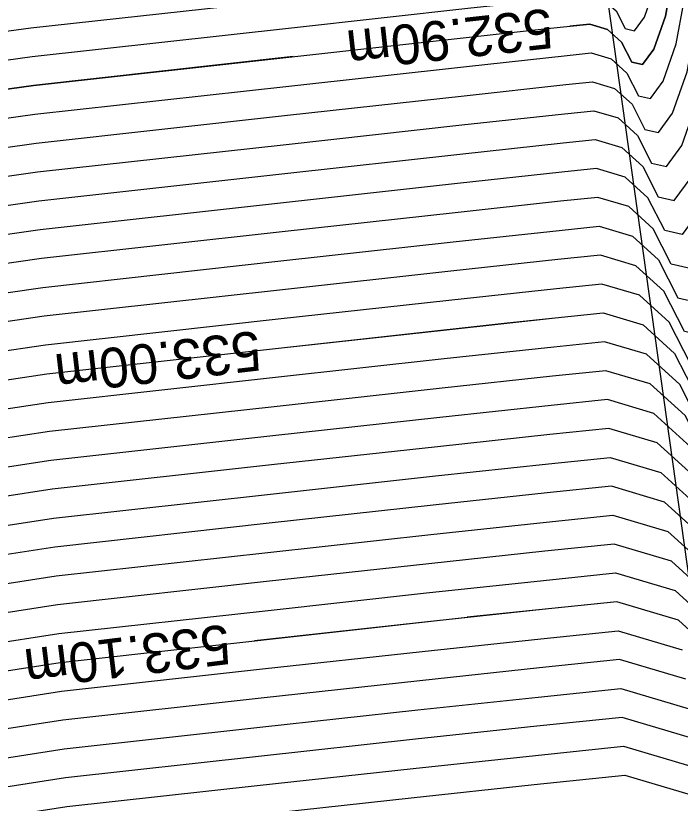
# Model space of a CAD drawing. Extents: x -866683 to -866410, y -1041951 to -1040252.
# Drawn here: x -866459.87 to -866454.85, y -1041930.1 to -1041924.15 of the extents above; entities that cross this region are included whole.
import ezdxf

# ---------------------------------------------------------------- set-up
doc = ezdxf.new("R2010")
doc.units = 0
for name, color, linetype in [('BREAKLINE', 7, 'Continuous'), ('V-HL', 7, 'Continuous'), ('V-VEDL', 7, 'Continuous'), ('V_po_cm', 7, 'Continuous')]:
    doc.layers.add(name, color=color, linetype=linetype)

msp = doc.modelspace()

# ---------------------------------------------------------------- linework, layer by layer
at = {"layer": 'BREAKLINE'}
msp.add_lwpolyline([(-866451.679, -1041950.508), (-866455.618, -1041922.473), (-866456.719, -1041912.396), (-866455.207, -1041909.853), (-866453.752, -1041908.342), (-866450, -1041907.538), (-866447.7, -1041908.076), (-866445.165, -1041909.459), (-866437.422, -1041915.176), (-866426.565, -1041925.108), (-866438.22, -1041915.868), (-866445.312, -1041910.554), (-866447.7, -1041908.076)], dxfattribs=at)
at = {"layer": 'V-HL'}
for points in [[(-866456.1597, -1041926.4733), (-866455.4344, -1041926.3983), (-866455.1343, -1041926.4876), (-866454.8967, -1041926.7037), (-866454.7217, -1041927.0466), (-866454.5387, -1041927.0874), (-866454.3478, -1041926.8261), (-866454.1489, -1041926.2626), (-866454.1234, -1041926.1239)], [(-866461.9223, -1041927.5304), (-866461.5568, -1041927.2112), (-866460.8556, -1041927.0405), (-866459.6359, -1041926.8588), (-866456.1597, -1041926.4733)]]:
    msp.add_lwpolyline(points, dxfattribs=at)
at = {"layer": 'V-VEDL'}
for points in [[(-866455.8588, -1041924.2509), (-866455.5364, -1041924.2176), (-866455.403, -1041924.2573), (-866455.2974, -1041924.3533), (-866455.2196, -1041924.5057), (-866455.1383, -1041924.5239), (-866455.0534, -1041924.4077), (-866454.9651, -1041924.1572), (-866454.9139, -1041923.8786), (-866454.9, -1041923.5718), (-866454.9234, -1041923.2368), (-866454.3666, -1041923.0849), (-866453.2296, -1041923.1162), (-866449.7953, -1041923.5448)], [(-866449.7169, -1041924.4172), (-866452.0847, -1041924.1217), (-866452.8467, -1041924.414), (-866453.1868, -1041925.1464), (-866453.1051, -1041926.3188), (-866453.1537, -1041927.3927), (-866453.3327, -1041928.3679), (-866453.6421, -1041929.2445), (-866453.9391, -1041929.651), (-866454.2237, -1041929.5876), (-866454.496, -1041929.0541), (-866454.8656, -1041928.7179), (-866455.3324, -1041928.579), (-866456.4607, -1041928.6957)], [(-866462.1228, -1041925.2864), (-866461.8248, -1041925.0261), (-866461.0792, -1041924.8677), (-866459.7368, -1041924.6809), (-866455.8588, -1041924.2509)], [(-866465.5755, -1041931.3671), (-866464.7785, -1041933.0499), (-866464.3707, -1041933.5335), (-866463.9536, -1041933.6594), (-866463.5272, -1041933.4274), (-866463.09, -1041933.2561), (-866462.6419, -1041933.1454), (-866462.1831, -1041933.0953), (-866461.8794, -1041932.6906), (-866461.731, -1041931.9311), (-866461.7378, -1041930.817), (-866461.7316, -1041930.0749), (-866461.7123, -1041929.7051), (-866461.68, -1041929.7074), (-866461.5945, -1041929.6531), (-866461.4558, -1041929.5422), (-866461.264, -1041929.3746), (-866460.6237, -1041929.2061), (-866459.535, -1041929.0366), (-866456.4607, -1041928.6957)]]:
    msp.add_lwpolyline(points, dxfattribs=at)
at = {"layer": 'V_po_cm'}
for points in [[(-866462.1629, -1041924.8375), (-866461.8784, -1041924.5891), (-866461.1239, -1041924.4331), (-866459.757, -1041924.2454), (-866457.7778, -1041924.0259), (-866456.418, -1041923.8754), (-866455.6777, -1041923.7939), (-866455.5568, -1041923.7814), (-866455.4568, -1041923.8112), (-866455.3776, -1041923.8832), (-866455.3192, -1041923.9975), (-866455.2582, -1041924.0111), (-866455.1946, -1041923.924), (-866455.1283, -1041923.7362), (-866455.0899, -1041923.5272), (-866455.0795, -1041923.2971), (-866455.097, -1041923.0459), (-866454.5186, -1041922.952), (-866453.3441, -1041923.0156), (-866451.5736, -1041923.2366), (-866450.2422, -1041923.3441), (-866449.3499, -1041923.3382), (-866448.8966, -1041923.2189)], [(-866462.1428, -1041925.062), (-866461.8516, -1041924.8076), (-866461.1015, -1041924.6504), (-866459.7469, -1041924.4632), (-866457.7878, -1041924.2459), (-866456.4347, -1041924.0962), (-866455.6876, -1041924.0141), (-866455.5466, -1041923.9995), (-866455.4299, -1041924.0342), (-866455.3375, -1041924.1183), (-866455.2694, -1041924.2516), (-866455.1983, -1041924.2675), (-866455.124, -1041924.1659), (-866455.0467, -1041923.9467), (-866455.0019, -1041923.7029), (-866454.9898, -1041923.4345), (-866455.0102, -1041923.1413), (-866454.4426, -1041923.0185), (-866453.2868, -1041923.0659), (-866451.543, -1041923.2835), (-866450.2317, -1041923.3894), (-866449.3528, -1041923.3836), (-866448.9063, -1041923.2661)], [(-866452.7723, -1041923.1732), (-866453.2296, -1041923.1162), (-866454.3666, -1041923.0849), (-866454.9234, -1041923.2368), (-866454.9, -1041923.5718), (-866454.9139, -1041923.8786), (-866454.9651, -1041924.1572), (-866455.0534, -1041924.4077), (-866455.1383, -1041924.5239), (-866455.2196, -1041924.5057), (-866455.2974, -1041924.3533), (-866455.403, -1041924.2573), (-866455.5364, -1041924.2176), (-866455.688, -1041924.2333)], [(-866462.1027, -1041925.5108), (-866461.798, -1041925.2446), (-866461.0568, -1041925.085), (-866459.7267, -1041924.8987), (-866457.8078, -1041924.6859), (-866456.4681, -1041924.5378), (-866455.7075, -1041924.4544), (-866455.5262, -1041924.4356), (-866455.3761, -1041924.4803), (-866455.2574, -1041924.5883), (-866455.1698, -1041924.7598), (-866455.0783, -1041924.7802), (-866454.9829, -1041924.6495), (-866454.8834, -1041924.3678), (-866454.8259, -1041924.0543), (-866454.8103, -1041923.7092), (-866454.8365, -1041923.3323), (-866454.2906, -1041923.1514), (-866453.1723, -1041923.1664), (-866451.4819, -1041923.3774), (-866450.2106, -1041923.4801), (-866449.3586, -1041923.4745), (-866448.9258, -1041923.3605)], [(-866462.0827, -1041925.7352), (-866461.7712, -1041925.4631), (-866461.0344, -1041925.3022), (-866459.7166, -1041925.1165), (-866457.8178, -1041924.906), (-866456.4847, -1041924.7586), (-866455.7175, -1041924.6745), (-866455.516, -1041924.6537), (-866455.3493, -1041924.7033), (-866455.2173, -1041924.8234), (-866455.12, -1041925.0139), (-866455.0184, -1041925.0366), (-866454.9123, -1041924.8914), (-866454.8018, -1041924.5783), (-866454.7379, -1041924.23), (-866454.7205, -1041923.8465), (-866454.7497, -1041923.4278), (-866454.2146, -1041923.2178), (-866453.1151, -1041923.2167), (-866451.4513, -1041923.4244), (-866450.2001, -1041923.5254), (-866449.3615, -1041923.5199), (-866448.9355, -1041923.4077)], [(-866462.0626, -1041925.9596), (-866461.7444, -1041925.6816), (-866461.0121, -1041925.5195), (-866459.7065, -1041925.3343), (-866457.8278, -1041925.126), (-866456.5014, -1041924.9794), (-866455.7274, -1041924.8947), (-866455.5058, -1041924.8718), (-866455.3224, -1041924.9263), (-866455.1772, -1041925.0584), (-866455.0702, -1041925.268), (-866454.9584, -1041925.2929), (-866454.8417, -1041925.1332), (-866454.7202, -1041924.7888), (-866454.6499, -1041924.4057), (-866454.6308, -1041923.9839), (-866454.6629, -1041923.5233), (-866454.1386, -1041923.2843), (-866453.0579, -1041923.267), (-866451.4207, -1041923.4713), (-866450.1896, -1041923.5708), (-866449.3644, -1041923.5653), (-866448.9453, -1041923.4549)], [(-866462.0426, -1041926.184), (-866461.7176, -1041925.9001), (-866460.9897, -1041925.7368), (-866459.6965, -1041925.5521), (-866457.8378, -1041925.346), (-866456.5181, -1041925.2002), (-866455.7374, -1041925.1149), (-866455.4956, -1041925.0898), (-866455.2955, -1041925.1494), (-866455.1371, -1041925.2935), (-866455.0204, -1041925.5221), (-866454.8985, -1041925.5493), (-866454.7712, -1041925.3751), (-866454.6386, -1041924.9994), (-866454.5619, -1041924.5814), (-866454.541, -1041924.1212), (-866454.5761, -1041923.6187), (-866454.0626, -1041923.3508), (-866453.0006, -1041923.3173), (-866451.3901, -1041923.5183), (-866450.179, -1041923.6161), (-866449.3673, -1041923.6107), (-866448.955, -1041923.5022)], [(-866448.9647, -1041923.5494), (-866449.3702, -1041923.6561), (-866450.1685, -1041923.6614), (-866451.3595, -1041923.5652), (-866452.9434, -1041923.3675), (-866453.9866, -1041923.4172), (-866454.4892, -1041923.7142), (-866454.4513, -1041924.2586), (-866454.4739, -1041924.7571), (-866454.557, -1041925.2099), (-866454.7006, -1041925.6169), (-866454.8385, -1041925.8056), (-866454.9707, -1041925.7762), (-866455.0971, -1041925.5285), (-866455.2687, -1041925.3724), (-866455.4854, -1041925.3079), (-866455.7473, -1041925.335), (-866456.5348, -1041925.421), (-866457.8478, -1041925.566), (-866459.6864, -1041925.7699), (-866460.9674, -1041925.9541), (-866461.6908, -1041926.1186), (-866462.0225, -1041926.4084)], [(-866448.9745, -1041923.5966), (-866449.3731, -1041923.7016), (-866450.158, -1041923.7067), (-866451.329, -1041923.6122), (-866452.8861, -1041923.4178), (-866453.9106, -1041923.4837), (-866454.4024, -1041923.8097), (-866454.3615, -1041924.3959), (-866454.3859, -1041924.9328), (-866454.4753, -1041925.4204), (-866454.63, -1041925.8587), (-866454.7785, -1041926.062), (-866454.9209, -1041926.0303), (-866455.057, -1041925.7635), (-866455.2418, -1041925.5954), (-866455.4752, -1041925.526), (-866455.7573, -1041925.5552), (-866456.5515, -1041925.6418), (-866457.8578, -1041925.786), (-866459.6763, -1041925.9876), (-866460.945, -1041926.1714), (-866461.664, -1041926.3371), (-866462.0025, -1041926.6328)], [(-866461.9824, -1041926.8572), (-866461.6372, -1041926.5556), (-866460.9226, -1041926.3886), (-866459.6662, -1041926.2054), (-866457.8678, -1041926.006), (-866456.5682, -1041925.8626), (-866455.7672, -1041925.7753), (-866455.465, -1041925.7441), (-866455.2149, -1041925.8185), (-866455.0169, -1041925.9986), (-866454.8711, -1041926.2844), (-866454.7186, -1041926.3184), (-866454.5595, -1041926.1006), (-866454.3937, -1041925.631), (-866454.2978, -1041925.1085), (-866454.2718, -1041924.5333), (-866454.3156, -1041923.9052), (-866453.8346, -1041923.5501), (-866452.8289, -1041923.4681), (-866451.2984, -1041923.6591), (-866450.1474, -1041923.7521), (-866449.376, -1041923.747), (-866448.9842, -1041923.6438)], [(-866448.9939, -1041923.691), (-866449.379, -1041923.7924), (-866450.1369, -1041923.7974), (-866451.2678, -1041923.7061), (-866452.7716, -1041923.5184), (-866453.7586, -1041923.6166), (-866454.2288, -1041924.0007), (-866454.182, -1041924.6706), (-866454.2098, -1041925.2842), (-866454.3121, -1041925.8415), (-866454.4889, -1041926.3424), (-866454.6586, -1041926.5747), (-866454.8213, -1041926.5385), (-866454.9769, -1041926.2336), (-866455.188, -1041926.0415), (-866455.4548, -1041925.9621), (-866455.7772, -1041925.9955), (-866456.5848, -1041926.0834), (-866457.8778, -1041926.226), (-866459.6561, -1041926.4232), (-866460.9003, -1041926.6059), (-866461.6104, -1041926.7741), (-866461.9624, -1041927.0816)], [(-866449.0037, -1041923.7382), (-866449.3819, -1041923.8378), (-866450.1264, -1041923.8427), (-866451.2372, -1041923.753), (-866452.7144, -1041923.5686), (-866453.6826, -1041923.683), (-866454.1419, -1041924.0961), (-866454.0923, -1041924.808), (-866454.1218, -1041925.4599), (-866454.2305, -1041926.052), (-866454.4183, -1041926.5842), (-866454.5986, -1041926.8311), (-866454.7715, -1041926.7926), (-866454.9368, -1041926.4687), (-866455.1612, -1041926.2645), (-866455.4446, -1041926.1802), (-866455.7871, -1041926.2156), (-866456.6015, -1041926.3042), (-866457.8878, -1041926.446), (-866459.646, -1041926.641), (-866460.8779, -1041926.8232), (-866461.5836, -1041926.9926), (-866461.9423, -1041927.306)], [(-866449.0232, -1041923.8327), (-866449.3877, -1041923.9286), (-866450.1053, -1041923.9334), (-866451.176, -1041923.8469), (-866452.5999, -1041923.6692), (-866453.5306, -1041923.8159), (-866453.9683, -1041924.2871), (-866453.9128, -1041925.0827), (-866453.9458, -1041925.8113), (-866454.0673, -1041926.4731), (-866454.2772, -1041927.0679), (-866454.4787, -1041927.3438), (-866454.6719, -1041927.3007), (-866454.8566, -1041926.9387), (-866455.1074, -1041926.7106), (-866455.4242, -1041926.6163), (-866455.807, -1041926.6559), (-866456.6349, -1041926.7458), (-866457.9078, -1041926.8861), (-866459.6258, -1041927.0766), (-866460.8332, -1041927.2578), (-866461.53, -1041927.4297), (-866461.9022, -1041927.7548)], [(-866449.0329, -1041923.8799), (-866449.3906, -1041923.9741), (-866450.0948, -1041923.9787), (-866451.1455, -1041923.8939), (-866452.5426, -1041923.7195), (-866453.4546, -1041923.8824), (-866453.8814, -1041924.3826), (-866453.8231, -1041925.22), (-866453.8578, -1041925.987), (-866453.9856, -1041926.6836), (-866454.2066, -1041927.3098), (-866454.4188, -1041927.6002), (-866454.6221, -1041927.5548), (-866454.8166, -1041927.1738), (-866455.0806, -1041926.9336), (-866455.414, -1041926.8344), (-866455.817, -1041926.8761), (-866456.6516, -1041926.9666), (-866457.9178, -1041927.1061), (-866459.6157, -1041927.2943), (-866460.8108, -1041927.475), (-866461.5031, -1041927.6482), (-866461.8822, -1041927.9793)], [(-866449.0426, -1041923.9271), (-866449.3935, -1041924.0195), (-866450.0843, -1041924.0241), (-866451.1149, -1041923.9408), (-866452.4854, -1041923.7698), (-866453.3786, -1041923.9488), (-866453.7946, -1041924.478), (-866453.7333, -1041925.3574), (-866453.7698, -1041926.1628), (-866453.904, -1041926.8942), (-866454.136, -1041927.5516), (-866454.3588, -1041927.8565), (-866454.5723, -1041927.8089), (-866454.7765, -1041927.4088), (-866455.0537, -1041927.1567), (-866455.4038, -1041927.0525), (-866455.8269, -1041927.0963), (-866456.6682, -1041927.1875), (-866457.9278, -1041927.3261), (-866459.6056, -1041927.5121), (-866460.7885, -1041927.6923), (-866461.4763, -1041927.8667), (-866461.8621, -1041928.2037)], [(-866449.0524, -1041923.9743), (-866449.3964, -1041924.0649), (-866450.0737, -1041924.0694), (-866451.0843, -1041923.9878), (-866452.4282, -1041923.82), (-866453.3026, -1041924.0153), (-866453.7078, -1041924.5735), (-866453.6436, -1041925.4947), (-866453.6818, -1041926.3385), (-866453.8224, -1041927.1047), (-866454.0655, -1041927.7934), (-866454.2988, -1041928.1129), (-866454.5225, -1041928.063), (-866454.7364, -1041927.6439), (-866455.0268, -1041927.3797), (-866455.3936, -1041927.2706), (-866455.8369, -1041927.3164), (-866456.6849, -1041927.4083), (-866457.9378, -1041927.5461), (-866459.5955, -1041927.7299), (-866460.7661, -1041927.9096), (-866461.4495, -1041928.0852), (-866461.8421, -1041928.4281)], [(-866461.822, -1041928.6525), (-866461.4227, -1041928.3037), (-866460.7437, -1041928.1269), (-866459.5854, -1041927.9477), (-866457.9478, -1041927.7661), (-866456.7016, -1041927.6291), (-866455.8468, -1041927.5366), (-866455.3834, -1041927.4886), (-866454.9999, -1041927.6027), (-866454.6964, -1041927.8789), (-866454.4727, -1041928.3171), (-866454.2389, -1041928.3692), (-866453.9949, -1041928.0353), (-866453.7408, -1041927.3152), (-866453.5938, -1041926.5142), (-866453.5538, -1041925.6321), (-866453.621, -1041924.669), (-866453.2267, -1041924.0817), (-866452.3709, -1041923.8703), (-866451.0537, -1041924.0347), (-866450.0632, -1041924.1147), (-866449.3993, -1041924.1103), (-866449.0621, -1041924.0215)], [(-866461.7885, -1041929.0808), (-866461.77, -1041929.0821), (-866461.6974, -1041929.0245), (-866461.5614, -1041928.9087), (-866461.3621, -1041928.7345), (-866460.6967, -1041928.5594), (-866459.5653, -1041928.3833), (-866457.9678, -1041928.2061), (-866456.735, -1041928.0707), (-866455.8667, -1041927.9769), (-866455.363, -1041927.9248), (-866454.9462, -1041928.0488), (-866454.6162, -1041928.349), (-866454.3731, -1041928.8253), (-866454.119, -1041928.8819), (-866453.8538, -1041928.5189), (-866453.5776, -1041927.7363), (-866453.4177, -1041926.8656), (-866453.3743, -1041925.9068), (-866453.4473, -1041924.86), (-866453.0747, -1041924.2146), (-866452.2564, -1041923.9709)], [(-866453.1507, -1041924.1482), (-866453.5341, -1041924.7645), (-866453.4641, -1041925.7694), (-866453.5057, -1041926.6899), (-866453.6592, -1041927.5257), (-866453.9243, -1041928.2771), (-866454.1789, -1041928.6256), (-866454.4229, -1041928.5712), (-866454.6563, -1041928.1139), (-866454.9731, -1041927.8258), (-866455.3732, -1041927.7067), (-866455.8568, -1041927.7567), (-866456.7183, -1041927.8499), (-866457.9578, -1041927.9861), (-866459.5754, -1041928.1655), (-866460.721, -1041928.3438), (-866461.3947, -1041928.5212), (-866461.5966, -1041928.6975), (-866461.7317, -1041928.815), (-866461.8, -1041928.8737), (-866461.8031, -1041928.8735)], [(-866457.7754, -1041924.4635), (-866457.7978, -1041924.4659), (-866459.7368, -1041924.6809), (-866461.0792, -1041924.8677), (-866461.8248, -1041925.0261), (-866462.1228, -1041925.2864)], [(-866457.8867, -1041926.6648), (-866456.6182, -1041926.525), (-866455.7971, -1041926.4358), (-866455.4344, -1041926.3983), (-866455.1343, -1041926.4876), (-866454.8967, -1041926.7037), (-866454.7217, -1041927.0466), (-866454.5387, -1041927.0874), (-866454.3478, -1041926.8261), (-866454.2839, -1041926.645)], [(-866454.5761, -1041928.584), (-866454.9193, -1041928.2718), (-866455.3528, -1041928.1428), (-866455.8767, -1041928.197), (-866456.7517, -1041928.2915), (-866457.9778, -1041928.4261), (-866459.5552, -1041928.601), (-866460.6723, -1041928.775), (-866461.3294, -1041928.9479), (-866461.5262, -1041929.1198), (-866461.6631, -1041929.234), (-866461.74, -1041929.2906), (-866461.7739, -1041929.2881)], [(-866461.7592, -1041929.4955), (-866461.71, -1041929.499), (-866461.6288, -1041929.4436), (-866461.491, -1041929.331), (-866461.2967, -1041929.1613), (-866460.648, -1041928.9905), (-866459.5451, -1041928.8188), (-866457.9878, -1041928.6461), (-866456.7683, -1041928.5123), (-866455.8866, -1041928.4172), (-866455.3426, -1041928.3609), (-866454.8924, -1041928.4949), (-866454.5361, -1041928.819)], [(-866454.8587, -1041928.7242), (-866454.8656, -1041928.7179), (-866455.3324, -1041928.579), (-866455.8966, -1041928.6373), (-866456.785, -1041928.7331), (-866457.9978, -1041928.8662), (-866458.0675, -1041928.8739)], [(-866461.73, -1041929.9101), (-866461.65, -1041929.9158), (-866461.5602, -1041929.8626), (-866461.4206, -1041929.7533), (-866461.2313, -1041929.588), (-866460.5994, -1041929.4217), (-866459.5249, -1041929.2544), (-866458.0078, -1041929.0862), (-866456.8017, -1041928.9539), (-866455.9065, -1041928.8575), (-866455.3222, -1041928.797), (-866454.8387, -1041928.9409)], [(-866454.8118, -1041929.164), (-866455.312, -1041929.0151), (-866455.9164, -1041929.0776), (-866456.8184, -1041929.1747), (-866458.0178, -1041929.3062), (-866459.5148, -1041929.4722), (-866460.5751, -1041929.6372), (-866461.1986, -1041929.8013), (-866461.3854, -1041929.9645), (-866461.5259, -1041930.0722), (-866461.6199, -1041930.1243), (-866461.7154, -1041930.1174)], [(-866461.7008, -1041930.3248), (-866461.5899, -1041930.3327), (-866461.4915, -1041930.2817), (-866461.3502, -1041930.1757), (-866461.1659, -1041930.0147), (-866460.5507, -1041929.8528), (-866459.5047, -1041929.69), (-866458.0278, -1041929.5262), (-866456.8351, -1041929.3955), (-866455.9264, -1041929.2978), (-866455.3018, -1041929.2332), (-866454.785, -1041929.387)], [(-866454.7581, -1041929.61), (-866455.2916, -1041929.4513), (-866455.9363, -1041929.518), (-866456.8517, -1041929.6163), (-866458.0378, -1041929.7462), (-866459.4946, -1041929.9077), (-866460.5264, -1041930.0684), (-866461.1332, -1041930.2281), (-866461.315, -1041930.3869), (-866461.4572, -1041930.4912), (-866461.5599, -1041930.5411), (-866461.6862, -1041930.5321)], [(-866461.6716, -1041930.7394), (-866461.5299, -1041930.7496), (-866461.4229, -1041930.7008), (-866461.2798, -1041930.598), (-866461.1005, -1041930.4414), (-866460.5021, -1041930.2839), (-866459.4845, -1041930.1255), (-866458.0478, -1041929.9662), (-866456.8684, -1041929.8371), (-866455.9463, -1041929.7381), (-866455.2814, -1041929.6693), (-866454.7312, -1041929.833)], [(-866461.657, -1041930.9468), (-866461.4999, -1041930.958), (-866461.3886, -1041930.9103), (-866461.2446, -1041930.8092), (-866461.0678, -1041930.6548), (-866460.4778, -1041930.4995), (-866459.4744, -1041930.3433), (-866458.0578, -1041930.1862), (-866456.8851, -1041930.0579), (-866455.9562, -1041929.9583), (-866455.2712, -1041929.8874), (-866454.7043, -1041930.0561)]]:
    msp.add_lwpolyline(points, dxfattribs=at)

# ---------------------------------------------------------------- texts
for s, rotation, p in [('532.90m', 186.2934, (-866455.8337, -1041924.0984)), ('533.00m', 186.67503, (-866458.0382, -1041926.5315)), ('533.10m', 187.07638, (-866458.2706, -1041928.7479))]:
    msp.add_text(s, height=0.3, rotation=rotation, dxfattribs=at).set_placement(p)

doc.saveas('drawing.dxf')
